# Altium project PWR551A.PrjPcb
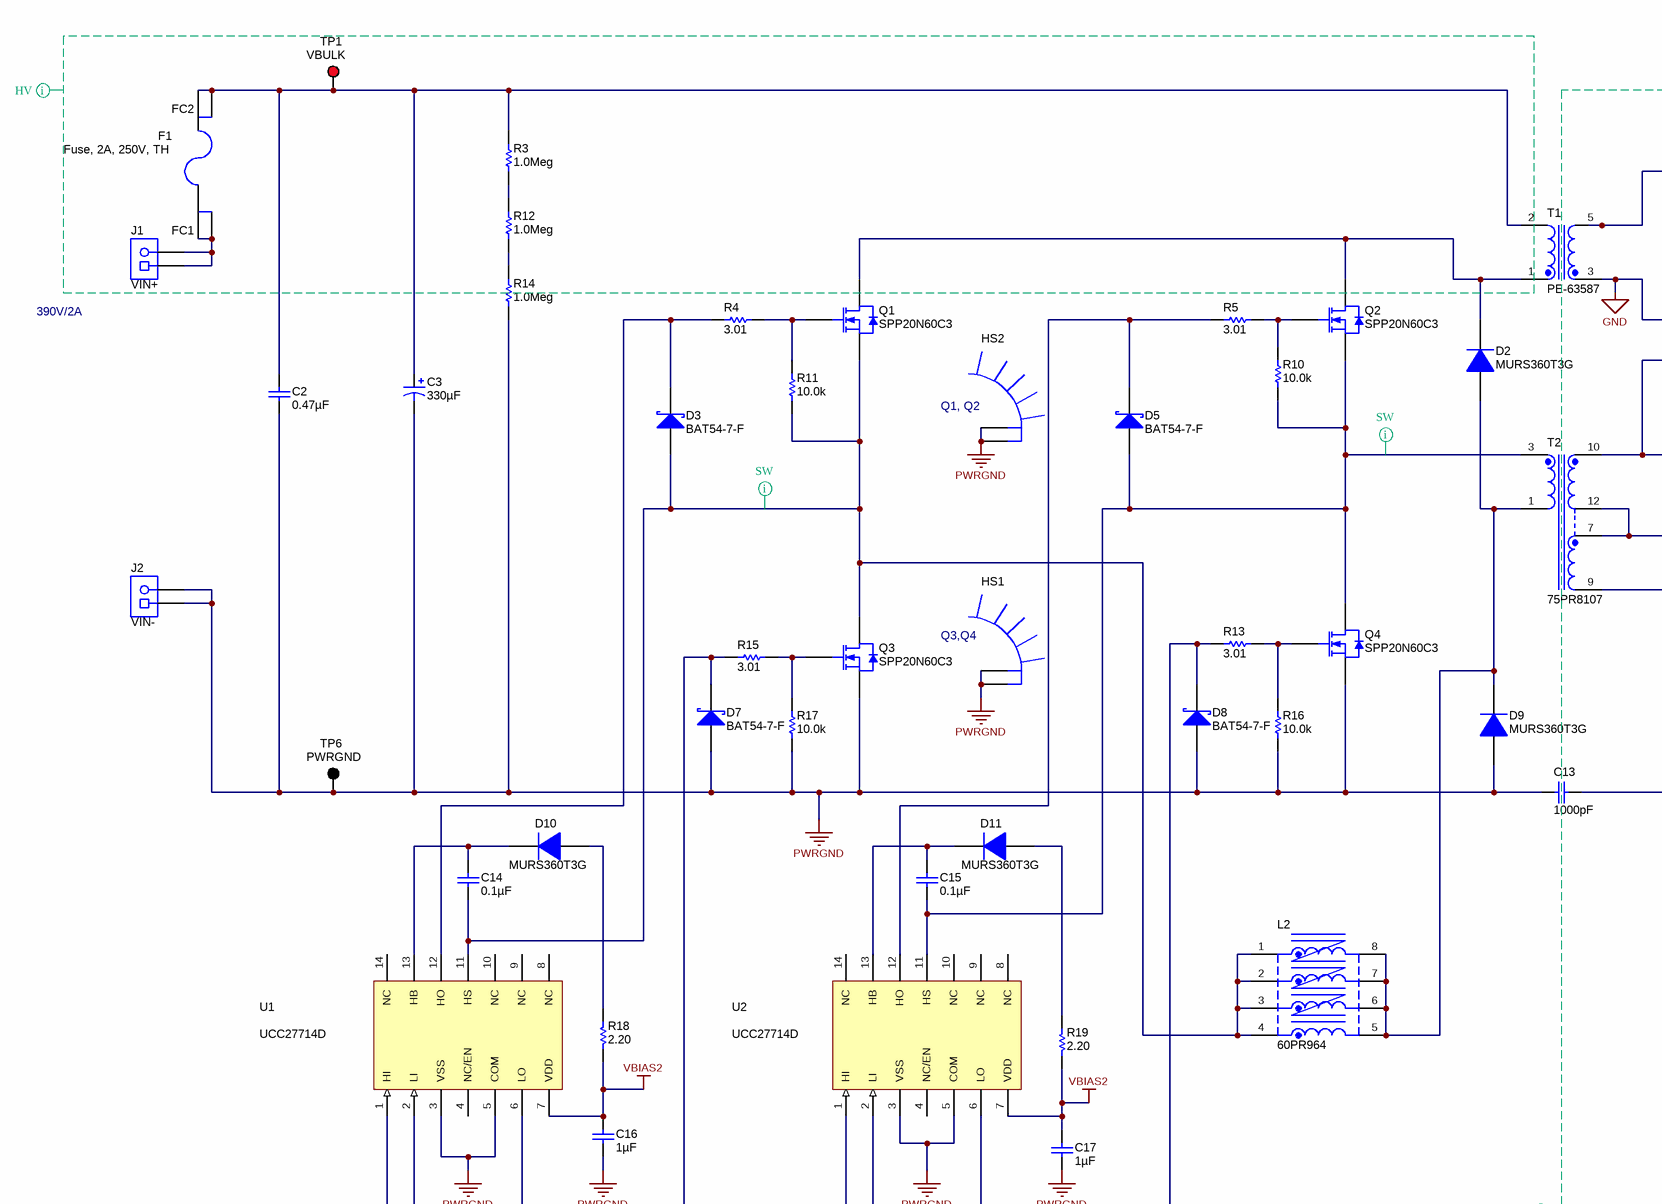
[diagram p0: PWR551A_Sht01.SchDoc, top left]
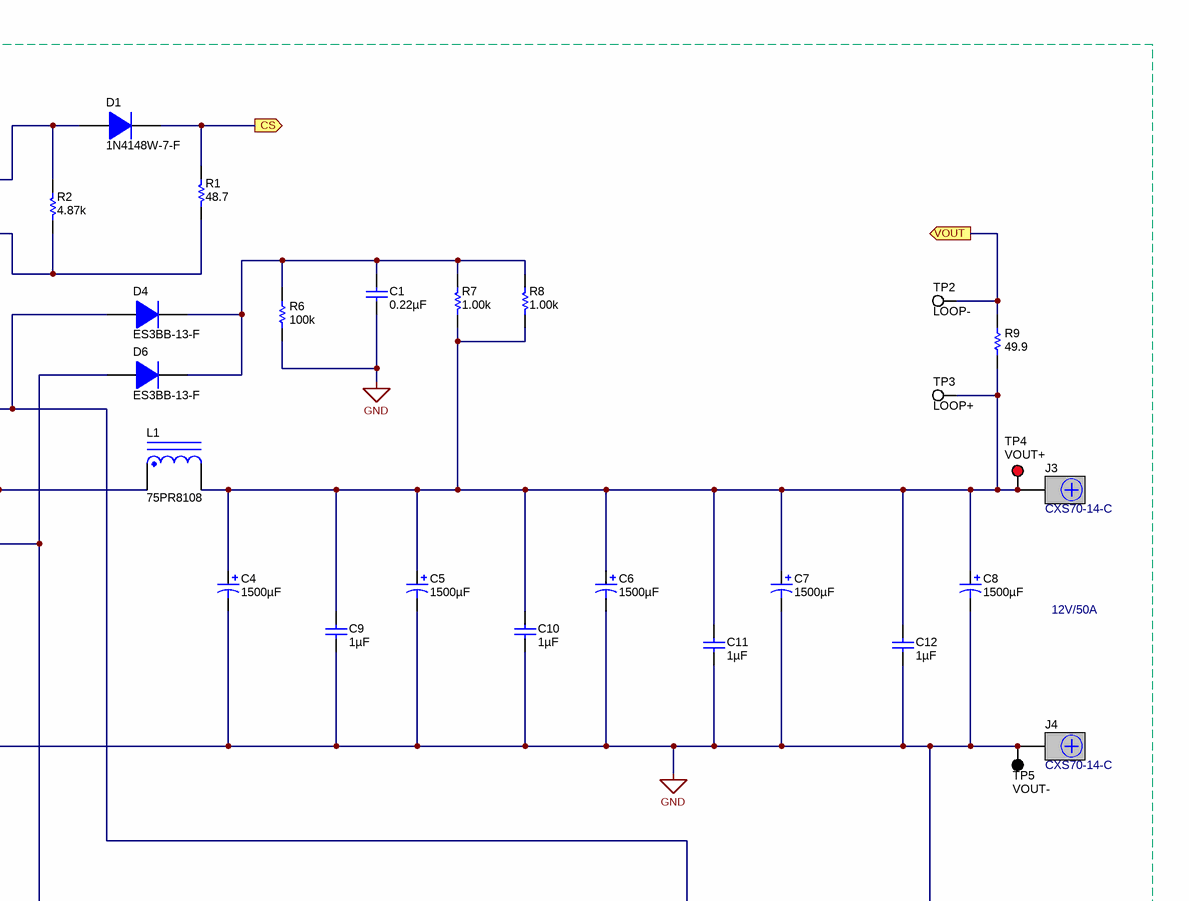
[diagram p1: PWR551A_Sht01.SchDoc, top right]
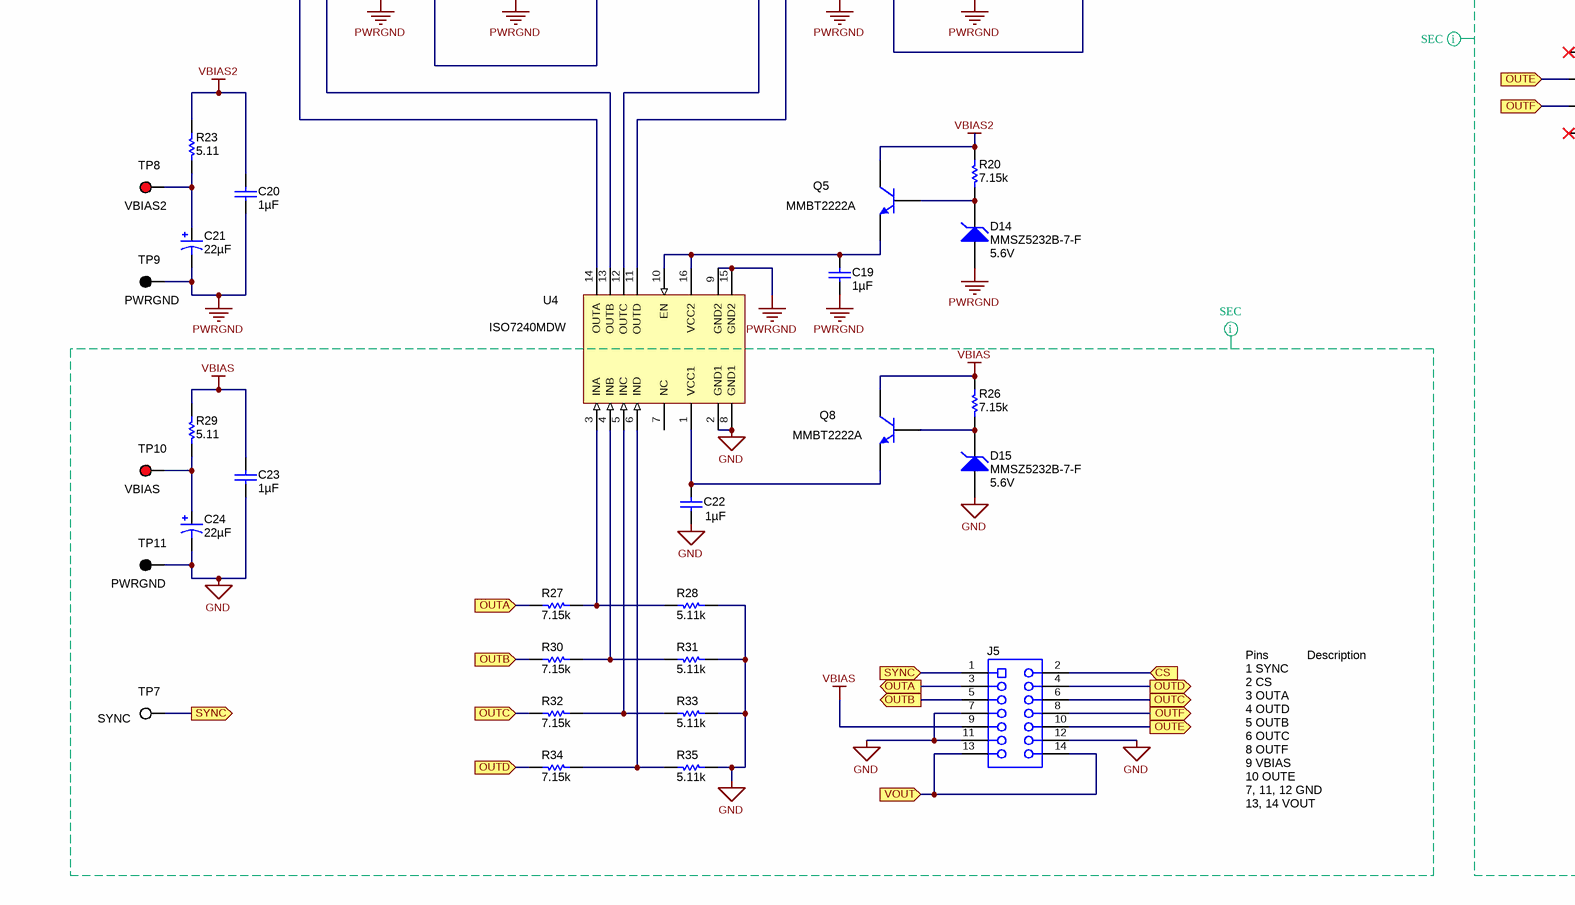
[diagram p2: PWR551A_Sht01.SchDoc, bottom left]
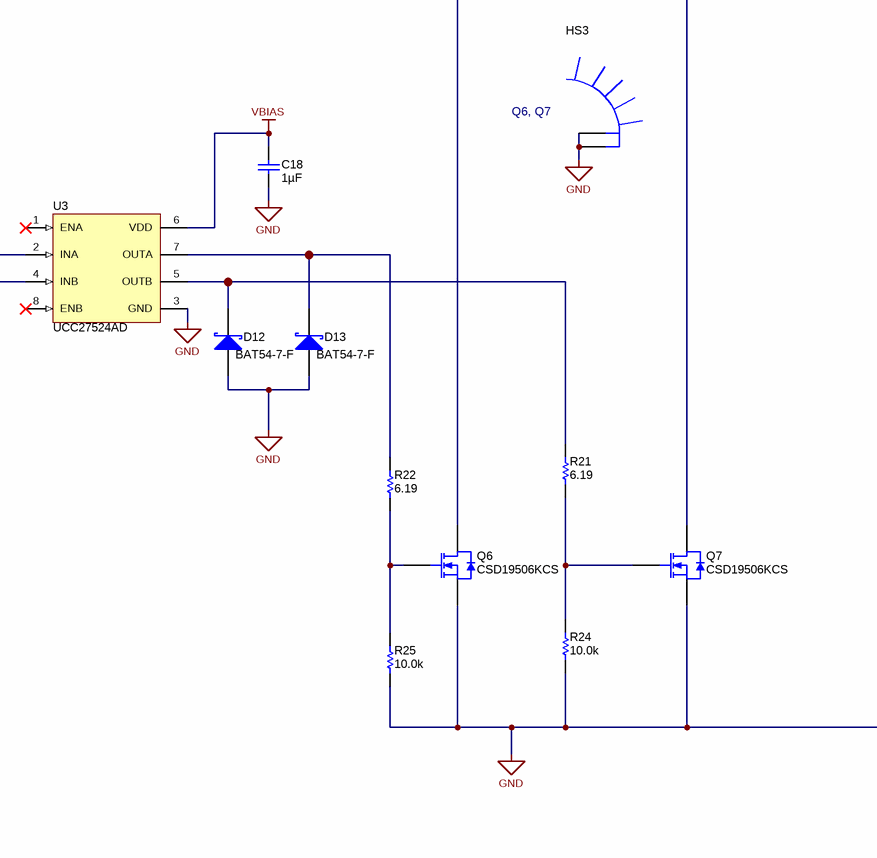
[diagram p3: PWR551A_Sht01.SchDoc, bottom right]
CopyrightYear: 2014; PCB_Layout: Brian Gaynor/Michael Rodgers; PCB_Rev: A; PRJ_Customer: Public Release; PRJ_Engineer: Mike O'Loughlin; PRJ_Number: PWR551; PRJ_Title: UCC27714EVM-551; SCH_Rev: A; TechSupport: http://www.ti.com/support
2 sheets, 162 parts. Net scope: flat (ports and power ports of the same name join across sheets).
Board file: PWR551A.PcbDoc
Sheets:
  PWR551A_Sht01.SchDoc
  PWR551A_Hardware.SchDoc

## Sheet PWR551A_Sht01.SchDoc
size 558 x 431 mm; Date: Not shown in title block; ApprovedBy: Not shown in title block; CheckedBy: Not shown in title block; Author: Not shown in title block; CompanyName: Not shown in title block; DrawnBy: Mike O'Loughlin; Engineer: Not shown in title block; Organization: Not shown in title block; Address1: Not shown in title block; Address2: Not shown in title block; Address3: Not shown in title block; Address4: Not shown in title block; DocumentNumber: 1; Revision: Use project parameter SCH_Rev; SheetNumber: 1; SheetTotal: 2; PageSetup: Record=PageOptions|CenterHorizontal=True|CenterVertical=True|PrintScale=1.00|XCorrection=1.00|YCorrection=1.00|PrintKind=0|BorderSize=5000000|LeftOffset=0|BottomOffset=0|Orientation=2|PaperLength=1000|PaperWidth=1000|Scale=100|PaperSource=15|PrintQuality=600|MediaType=1|DitherType=10|PaperKind=Letter|PrintScaleMode=1

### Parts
C1  ValueDisplayed: 0.22µF  [2220]  (hidden comment: C2220C224J1GACTU)
C2  ValueDisplayed: 0.47µF  [CAPRR2250W80L2550T850H1750]  (hidden comment: ECQ-U2A474ML)
C3  ValueDisplayed: 330µF  [TS-HC_3500x3500]  (hidden comment: EET-HC2W331EA)
C4  ValueDisplayed: 1500µF  [KY_1000x3000]  (hidden comment: EKY-160ELL152MJ30S)
C5  ValueDisplayed: 1500µF  [KY_1000x3000]  (hidden comment: EKY-160ELL152MJ30S)
C6  ValueDisplayed: 1500µF  [KY_1000x3000]  (hidden comment: EKY-160ELL152MJ30S)
C7  ValueDisplayed: 1500µF  [KY_1000x3000]  (hidden comment: EKY-160ELL152MJ30S)
C8  ValueDisplayed: 1500µF  [KY_1000x3000]  (hidden comment: EKY-160ELL152MJ30S)
C9  ValueDisplayed: 1µF  [1206]  (hidden comment: C3216X7R1E105K085AA)
C10  ValueDisplayed: 1µF  [1206]  (hidden comment: C3216X7R1E105K085AA)
C11  ValueDisplayed: 1µF  [1206]  (hidden comment: C3216X7R1E105K085AA)
C12  ValueDisplayed: 1µF  [1206]  (hidden comment: C3216X7R1E105K085AA)
C13  ValueDisplayed: 1000pF  [440L_930x1250]  (hidden comment: 440LD10-R)
C14  ValueDisplayed: 0.1µF  [0805_HV]  (hidden comment: C2012X7R1H104K)
C15  ValueDisplayed: 0.1µF  [0805_HV]  (hidden comment: C2012X7R1H104K)
C16  ValueDisplayed: 1µF  [0805_HV]  (hidden comment: C2012X7R1E105K)
C17  ValueDisplayed: 1µF  [0805_HV]  (hidden comment: C2012X7R1E105K)
C18  ValueDisplayed: 1µF  [0805_HV]  (hidden comment: C2012X7R1E105K)
C19  ValueDisplayed: 1µF  [0805_HV]  (hidden comment: C2012X7R1E105K)
C20  ValueDisplayed: 1µF  [0805_HV]  (hidden comment: C2012X7R1E105K)
C21  ValueDisplayed: 22µF  [M_500x1100]  (hidden comment: ECA-1VM220)
C22  ValueDisplayed: 1µF  [0805_HV]  (hidden comment: C2012X7R1E105K)
C23  ValueDisplayed: 1µF  [0805_HV]  (hidden comment: C2012X7R1E105K)
C24  ValueDisplayed: 22µF  [M_500x1100]  (hidden comment: ECA-1VM220)
D1  1N4148W-7-F  [SOD-123]
D2  MURS360T3G  [SMC]
D3  BAT54-7-F  [SOT-23]
D4  ES3BB-13-F  [SMB]
D5  BAT54-7-F  [SOT-23]
D6  ES3BB-13-F  [SMB]
D7  BAT54-7-F  [SOT-23]
D8  BAT54-7-F  [SOT-23]
D9  MURS360T3G  [SMC]
D10  MURS360T3G  [SMC]
D11  MURS360T3G  [SMC]
D12  BAT54-7-F  [SOT-23]
D13  BAT54-7-F  [SOT-23]
D14  MMSZ5232B-7-F  value 5.6V  [SOD-123]
D15  MMSZ5232B-7-F  value 5.6V  [SOD-123]
F1  Fuse, 2A, 250V, TH  (mechanical)
FC1  01000056Z  [Littelfuse_0100-0020_54_56]  (value not drawn)
FC2  01000056Z  [Littelfuse_0100-0020_54_56]  (value not drawn)
HS1  782653B02000G  [HEATSINK_782653B02000G]  (value not drawn)
HS2  782653B02000G  [HEATSINK_782653B02000G]  (value not drawn)
HS3  782653B02000G  [HEATSINK_782653B02000G]  (value not drawn)
J1  VIN+  [CONN_ED120-2DS]
J2  VIN-  [CONN_ED120-2DS]
J3  CXS70-14-C  [Panduit_CXS70-14-C]
J4  CXS70-14-C  [Panduit_CXS70-14-C]
J5  DF11-14DS-2DSA(05)  [Hirose_DF11-14DS-2DSA[05]]  (value not drawn)
L1  75PR8108  [75P]
L2  60PR964  [60P]
Q1  SPP20N60C3  [TO-220AB_100mil]
Q2  SPP20N60C3  [TO-220AB_100mil]
Q3  SPP20N60C3  [TO-220AB_100mil]
Q4  SPP20N60C3  [TO-220AB_100mil]
Q5  MMBT2222A  [SOT-23]
Q6  CSD19506KCS  [TO-220AB_100mil]
Q7  CSD19506KCS  [TO-220AB_100mil]
Q8  MMBT2222A  [SOT-23]
R1  value 48.7  [0805_HV]  (hidden comment: CRCW080548R7FKEA)
R2  value 4.87k  [0805_HV]  (hidden comment: ERJ-6ENF4871V)
R3  value 1.0Meg  [1206]  (hidden comment: CRCW12061M00JNEA)
R4  value 3.01  [0805_HV]  (hidden comment: CRCW08053R01FKEA)
R5  value 3.01  [0805_HV]  (hidden comment: CRCW08053R01FKEA)
R6  ValueDisplayed: 100k  [2512]  (hidden comment: CRCW2512100KFKEG)
R7  value 1.00k  [4527_450]  (hidden comment: WSC45271K000FEA)
R8  value 1.00k  [4527_450]  (hidden comment: WSC45271K000FEA)
R9  ValueDisplayed: 49.9  [0805_HV]  (hidden comment: ERJ-6ENF49R9V)
R10  value 10.0k  [0805_HV]  (hidden comment: ERJ-6ENF1002V)
R11  value 10.0k  [0805_HV]  (hidden comment: ERJ-6ENF1002V)
R12  value 1.0Meg  [1206]  (hidden comment: CRCW12061M00JNEA)
R13  value 3.01  [0805_HV]  (hidden comment: CRCW08053R01FKEA)
R14  value 1.0Meg  [1206]  (hidden comment: CRCW12061M00JNEA)
R15  value 3.01  [0805_HV]  (hidden comment: CRCW08053R01FKEA)
R16  value 10.0k  [0805_HV]  (hidden comment: ERJ-6ENF1002V)
R17  value 10.0k  [0805_HV]  (hidden comment: ERJ-6ENF1002V)
R18  value 2.20  [0805_HV]  (hidden comment: ERJ-6RQF2R2V)
R19  value 2.20  [0805_HV]  (hidden comment: ERJ-6RQF2R2V)
R20  value 7.15k  [0805_HV]  (hidden comment: ERJ-6ENF7151V)
R21  value 6.19  [0805_HV]  (hidden comment: CRCW08056R19FKEA)
R22  value 6.19  [0805_HV]  (hidden comment: CRCW08056R19FKEA)
R23  value 5.11  [0805_HV]  (hidden comment: CRCW08055R11FKEA)
R24  value 10.0k  [0805_HV]  (hidden comment: ERJ-6ENF1002V)
R25  value 10.0k  [0805_HV]  (hidden comment: ERJ-6ENF1002V)
R26  value 7.15k  [0805_HV]  (hidden comment: ERJ-6ENF7151V)
R27  value 7.15k  [0805_HV]  (hidden comment: ERJ-6ENF7151V)
R28  value 5.11k  [0805_HV]  (hidden comment: ERJ-6ENF5111V)
R29  value 5.11  [0805_HV]  (hidden comment: CRCW08055R11FKEA)
R30  value 7.15k  [0805_HV]  (hidden comment: ERJ-6ENF7151V)
R31  value 5.11k  [0805_HV]  (hidden comment: ERJ-6ENF5111V)
R32  value 7.15k  [0805_HV]  (hidden comment: ERJ-6ENF7151V)
R33  value 5.11k  [0805_HV]  (hidden comment: ERJ-6ENF5111V)
R34  value 7.15k  [0805_HV]  (hidden comment: ERJ-6ENF7151V)
R35  value 5.11k  [0805_HV]  (hidden comment: ERJ-6ENF5111V)
T1  PE-63587  [Pulse_PE6358X]
T2  75PR8107  [VITEC_75PR8107]
TP1  VBULK  [Keystone5000]
TP2  LOOP-  [Keystone5002]
TP3  LOOP+  [Keystone5002]
TP4  VOUT+  [Keystone5000]
TP5  VOUT-  [Keystone5001]
TP6  PWRGND  [Keystone5001]
TP7  SYNC  [Keystone5002]
TP8  VBIAS2  [Keystone5000]
TP9  PWRGND  [Keystone5001]
TP10  VBIAS  [Keystone5000]
TP11  PWRGND  [Keystone5001]
U1  UCC27714D  [D0014A_N]
U2  UCC27714D  [D0014A_N]
U3  UCC27524AD  [D0008A_N]
U4  ISO7240MDW  [DW0016A_N]

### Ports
CS (in), CS (out), OUTA (in), OUTA (out), OUTB (in), OUTB (out), OUTC (in), OUTC (out), OUTD (in), OUTD (out), OUTE (in), OUTE (out), OUTF (in), OUTF (out), SYNC (in), SYNC (out), VOUT (in), VOUT (out)

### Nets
GND: C1.1 C4.2(-) C5.2(-) C6.2(-) C7.2(-) C8.2(-) C9.1 C10.1 C11.1 C12.1 C13.1 C18.1 C22.1 C23.1 C24.2(-) D12.1(A) D13.1(A) D15.2(A) HS3.1 HS3.2 J4.1 J5.7 J5.11 J5.12 Q6.3(S) Q7.3(S) R1.2 R2.2 R6.2 R24.2 R25.2 R28.1 R31.1 R33.1 R35.1 T1.3 TP5.1 TP11.1 U3.3(GND) U4.2(GND1) U4.8(GND1)
PWRGND: C2.1 C3.2(-) C13.2 C16.1 C17.1 C19.1 C20.1 C21.2(-) D7.1(A) D8.1(A) D9.2(A) D14.2(A) HS1.1 HS1.2 HS2.1 HS2.2 J2.1 J2.2 Q3.3(S) Q4.3(S) R14.1 R16.2 R17.2 TP6.1 TP9.1 U1.3(VSS) U1.5(COM) U2.3(VSS) U2.5(COM) U4.9(GND2) U4.15(GND2)
VBIAS: C18.2 C23.2 J5.9 Q8.3(C) R26.1 R29.1 U3.6(VDD)
VBIAS2: C16.2 C17.2 C20.2 Q5.3(C) R18.1 R19.1 R20.1 R23.1 U1.7(VDD) U2.7(VDD)
CS: D1.1(K) J5.2 R1.1 ; port CS
OUTA: J5.3 R27.1 ; port OUTA
OUTB: J5.5 R30.1 ; port OUTB
OUTC: J5.6 R32.1 ; port OUTC
OUTD: J5.4 R34.1 ; port OUTD
OUTE: J5.10 U3.2(INA) ; port OUTE
OUTF: J5.8 U3.4(INB) ; port OUTF
SYNC: J5.1 TP7.1 ; port SYNC
VOUT: J5.13 J5.14 R9.1 TP2.1 ; port VOUT
NetC1_2: C1.2 D4.1(K) D6.1(K) R6.1 R7.2 R8.2
NetC2_2: C2.2 C3.1(+) FC2.1 FC2.2 R3.2 T1.2 TP1.1
NetC4_1: C4.1(+) C5.1(+) C6.1(+) C7.1(+) C8.1(+) C9.2 C10.2 C11.2 C12.2 J3.1 L1.14 R7.1 R8.1 R9.2 TP3.1 TP4.1
NetC14_1: C14.1 D3.1(A) L2.1 L2.2 L2.3 L2.4 Q1.3(S) Q3.2(D) R11.2 U1.11(HS)
NetC14_2: C14.2 D10.1(K) U1.13(HB)
NetC15_1: C15.1 D5.1(A) Q2.3(S) Q4.2(D) R10.1 T2.3 U2.11(HS)
NetC15_2: C15.2 D11.1(K) U2.13(HB)
NetC19_2: C19.2 Q5.2(E) U4.10(EN) U4.16(VCC2)
NetC21_1: C21.1(+) R23.2 TP8.1
NetC22_2: C22.2 Q8.2(E) U4.1(VCC1)
NetC24_1: C24.1(+) R29.2 TP10.1
NetD1_2: D1.2(A) R2.1 T1.5
NetD2_1: D2.1(K) Q1.2(D) Q2.2(D) T1.1
NetD2_2: D2.2(A) D9.1(K) L2.5 L2.6 L2.7 L2.8 T2.1
NetD3_3: D3.3(K) R4.1 U1.12(HO)
NetD4_2: D4.2(A) Q7.2(D) T2.10
NetD5_3: D5.3(K) R5.1 U2.12(HO)
NetD6_2: D6.2(A) Q6.2(D) T2.9
NetD7_3: D7.3(K) R15.1 U1.6(LO)
NetD8_3: D8.3(K) R13.1 U2.6(LO)
NetD10_2: D10.2(A) R18.2
NetD11_2: D11.2(A) R19.2
NetD12_3: D12.3(K) R21.1 U3.5(OUTB)
NetD13_3: D13.3(K) R22.1 U3.7(OUTA)
NetD14_1: D14.1(K) Q5.1(B) R20.2
NetD15_1: D15.1(K) Q8.1(B) R26.2
NetFC1_1: FC1.1 FC1.2 J1.1 J1.2
NetL1_13: L1.13 T2.7 T2.12
NetQ1_1: Q1.1(G) R4.2 R11.1
NetQ2_1: Q2.1(G) R5.2 R10.2
NetQ3_1: Q3.1(G) R15.2 R17.1
NetQ4_1: Q4.1(G) R13.2 R16.1
NetQ6_1: Q6.1(G) R22.2 R25.1
NetQ7_1: Q7.1(G) R21.2 R24.1
NetR3_1: R3.1 R12.2
NetR12_1: R12.1 R14.2
NetR27_2: R27.2 R28.2 U4.3(INA)
NetR30_2: R30.2 R31.2 U4.4(INB)
NetR32_2: R32.2 R33.2 U4.5(INC)
NetR34_2: R34.2 R35.2 U4.6(IND)
NetU1_1: U1.1(HI) U4.14(OUTA)
NetU1_2: U1.2(LI) U4.13(OUTB)
NetU2_1: U2.1(HI) U4.12(OUTC)
NetU2_2: U2.2(LI) U4.11(OUTD)

Not connected (* = marked no-connect by the designer): F1 1 2; U1 4(NC/EN) 8(NC) 9(NC) 10(NC) 14(NC); U2 4(NC/EN) 8(NC) 9(NC) 10(NC) 14(NC); U3 1(ENA)* 8(ENB)*; U4 7(NC)

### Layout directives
net class SEC: GND, VBIAS
net class HV: (no net found under the mark)
net class SW: NetC14_1, NetC15_1

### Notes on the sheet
- 390V/2A
- (near HS2) Q1, Q2
- (near HS1) Q3,Q4
- 12V/50A
- Q6, Q7
- Pins           Description
  1	SYNC
  2	CS
  3	OUTA
  4	OUTD
  5	OUTB
  6	OUTC
  8	OUTF
  9	VBIAS
  10	OUTE
  7, 11, 12	GND
  13, 14	VOUT

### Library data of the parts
C1 = C2220C224J1GACTU: CAP, CERM, 0.22uF, 100V, +/-5%, C0G/NP0, 2220; Manufacturer: Kemet; Polarized: N; CompType: Capacitor; U/M: EA; Cap_F: 0.00000022; Tolerance_%: 5; Value1: Unknown; VDC_V: 100; TaMin_C: -55; TaMax_C: 125
C2 = ECQ-U2A474ML: CAP, Film, 0.47uF, 275V, +/-20%, TH; Manufacturer: Panasonic; Polarized: N; CompType: Capacitor; U/M: EA; Cap_F: 0.00000047; Tolerance_%: 20; Value1: Unknown; VDC_V: 275; TaMin_C: -40; TaMax_C: 100; Cap_Case: Radial 25x8.5x18.5
C3 = EET-HC2W331EA: CAP, AL, 330uF, 450V, +/-20%, 0.553 ohm, TH; Manufacturer: Panasonic; Polarized: Y; CompType: Capacitor; U/M: EA; Cap_F: 0.00033; Tolerance_%: 20; VDC_V: 450; ESR_Ohm: 0.553; IRMS_A: 1.38; TaMin_C: -25; TaMax_C: 105; Cap_Case: 35x35
C4-C8 = EKY-160ELL152MJ30S: CAP, AL, 1500uF, 16V, +/-20%, 0.031 ohm, TH; Manufacturer: Nippon Chemi-Con; Polarized: Y; CompType: Capacitor; U/M: EA; Cap_F: 0.0015; Tolerance_%: 20; VDC_V: 16; ESR_Ohm: 0.031; IRMS_A: 1.91; TaMin_C: -40; TaMax_C: 105; Cap_Case: 10x30
C9-C12 = C3216X7R1E105K/0.85: CAP, CERM, 1 µF, 25 V, +/- 10%, X7R, 1206; Manufacturer: TDK; Value: 1uF; Polarized: N; CompType: Capacitor; U/M: EA; Cap_F: 0.000001; Tolerance_%: 10; ESR_ohm: 0.01; Value1: 0.01 ohm; VDC_V: 25; Value2: 25V; TaMin_C: -55; TaMax_C: 125
C13 = 440LD10-R: CAP, CERM, 1000pF, 400V, +/-20%, Y5U, Disc, 9.3x12.5mm; Manufacturer: Yageo America; Polarized: N; CompType: Capacitor; U/M: EA; Cap_F: 0.000000001; Tolerance_%: 20; Value1: Unknown; VDC_V: 400; TaMin_C: -30; TaMax_C: 125
C14 C15 = C2012X7R1H104K: CAP, CERM, 0.1uF, 50V, +/-10%, X7R, 0805; Manufacturer: TDK; Polarized: N; CompType: Capacitor; U/M: EA; Cap_F: 0.0000001; Tolerance_%: 10; Value1: Unknown; VDC_V: 50; TaMin_C: -55; TaMax_C: 125; Cap_Case: 0805
C16-C20 C22 C23 = C2012X7R1E105k: CAP, CERM, 1uF, 25V, +/-10%, X7R, 0805; Manufacturer: TDK; Polarized: N; CompType: Capacitor; U/M: EA; Cap_F: 0.000001; Tolerance_%: 10; ESR_Ohm: 0.0075; Value1: 0.0075 ohm; VDC_V: 25; TaMin_C: -55; TaMax_C: 125; Cap_Case: 0805
C21 C24 = ECA-1VM220: CAP, AL, 22uF, 35V, +/-20%, TH; Manufacturer: Panasonic; Polarized: Y; CompType: Capacitor; U/M: EA; Cap_F: 0.000022; Tolerance_%: 20; Value1: Unknown; VDC_V: 35; IRMS_A: 0.095; TaMin_C: -40; TaMax_C: 85; Cap_Case: 5x11
D1 = 1N4148W-7-F: Diode, Ultrafast, 100V, 0.15A, SOD-123; Manufacturer: Diodes Inc.; U/M: EA; Vf_V: 1.25; Value2: 1.25V; Io_A: 0.15; Vr_V: 100; TJmax_C: 150
D2 D9-D11 = MURS360T3G: Diode, Ultrafast, 600 V, 3 A, SMC; Manufacturer: ON Semiconductor; Value: 600V; U/M: EA; Vf_V: 1.25; Value1: 3A; Value2: 1.25V; Io_A: 3; Vr_V: 600; TJmax_C: 175; RJC_CperW: 11
D3 D5 D7 D8 D12 D13 = bat54-7-F: Diode, Schottky, 30V, 0.2A, SOT-23; Manufacturer: Diodes Inc.; U/M: EA; Vf_V: 0.65; Value2: 0.65V; Io_A: 0.2; Vr_V: 30; TJmax_C: 125
D4 D6 = ES3BB-13-F: Diode, Superfast Rectifier, 100V, 3A, SMB; Manufacturer: Diodes Inc.; U/M: EA; Vf_V: 0.9; Value2: 0.9V; Io_A: 3; Vr_V: 100
D14 D15 = MMSZ5232B-7-F: Diode, Zener, 5.6V, 500mW, SOD-123; Manufacturer: Diodes Inc.; SymbolCreator: a0412235; U/M: EA; Power_W: 0.5; Vz_V: 5.6; Value1: 0.5W; RJA_CperW: 350
F1 = BK/S501-2-R: Manufacturer: Cooper Bussman; U/M: EA; VDC_V: 250; Interrupt_AC: 1500; Irating_A: 2; Vdrop: 0.205
FC1 FC2 = 01000056Z: Fuse Holder, 10A, TH; Manufacturer: Littelfuse; SymbolCreator: a0411947
HS1-HS3 = 782653B02000G: HEATSINK VERT MAX CLIP, BLACK, 2 INCHES; Manufacturer: Aavid; SymbolCreator: a0799628
J1 J2 = ED120/2DS: TERMINAL BLOCK 5.08MM VERT 2POS, TH; Manufacturer: On-Shore Technology; SymbolCreator: a0412235; U/M: EA
J3 J4 = CXS70-14-C: Terminal 70A Lug; Manufacturer: Panduit; SymbolCreator: crossc; CompType: Screw Terminal; U/M: EA
J5 = DF11-14DS-2DSA(05): Receptacle, 7x2, 2mm, TH; Manufacturer: Hirose Electric Co. Ltd.; SymbolCreator: a0412235; U/M: EA
L1 = 75PR8108: Inductor, Shielded, ?, 2uH, A, 0.0009 ohm, TH; Manufacturer: Vitec Corporation; SymbolCreator: x0208325; Ind_H: 2.0E-6; ValueDisplayed: 2µH; DCR_ohm: 0.0009; U/M: EA
L2 = 60PR964: Inductor, Shielded, ?, 26uH, A, 0.027 ohm, TH; Manufacturer: Vitec Corporation; SymbolCreator: x0208325; Ind_H: 26.0E-6; ValueDisplayed: 26µH; DCR_ohm: 0.027; U/M: EA
Q1-Q4 = SPP20N60C3: MOSFET, N-CH, 650V, 20.7A, TO-220AB; Manufacturer: Infineon Technologies; Alternate Manufacturer: None; U/M: EA; ChType: N; VdsMax_V: 650; Value1: 0.19 ohm; Rdson45_Ohm: 0.19; Value2: 114 nC; QgTyp_nC: 114; Vgs_V: 3.9; IdsMax_A: 20.7
Q5 Q8 = MMBT2222A, Fairchild Semiconductor: Transistor, NPN, 40V, 0.15A, SOT-23; Value: 0.3V; CompType: BJT; PNP: 0; NPN: 1; Vceo_V: 40; Vcesat1_V: 0.3; IcRated_A: 0.15; HfeMax: 300; TaMin_C: -55; TaMax_C: 150; U/M: EA
Q6 Q7 = CSD19506KCS: MOSFET, N-CH, 80V, 100A, TO-220AB; Manufacturer: Texas Instruments; Alternate Manufacturer: None; U/M: EA; ChType: N; VdsMax_V: 80; Value1: ? ohm; Value2: 120 nC; QgTyp_nC: 120; Vgs_V: 20; IdsMax_A: 100
R1 = crcw080548r7fkea: RES, 48.7 ohm, 1%, 0.125W, 0805; Manufacturer: Vishay-Dale; CompType: Resistor; Value_Code: 48R7; Tolerance_%: 1; Power_W: 0.125; VDC_V: 150; TempCo: 100 ppm/C; EIA_Code: E96; U/M: EA
R2 = ERJ-6ENF4871V: RES, 4.87k ohm, 1%, 0.125W, 0805; Manufacturer: Panasonic; CompType: Resistor; Res_ohm: 4870; Value_Code: 4k87; Tolerance_%: 1; Power_W: 0.125; TempCo: 100 ppm/C; EIA_Code: E96; U/M: EA
R3 R12 R14 = CRCW12061M00JNEA: RES, 1.0Meg ohm, 5%, 0.25W, 1206; Manufacturer: Vishay-Dale; CompType: Resistor; Res_ohm: 1000000; Value_Code: 1M00; Tolerance_%: 5; Power_W: 0.25; VDC_V: 200; TempCo: 200 ppm/C; EIA_Code: E24; U/M: EA
R4 R5 R13 R15 = CRCW08053R01FKEA: RES, 3.01 ohm, 1%, 0.125W, 0805; Manufacturer: Vishay-Dale; CompType: Resistor; Value_Code: 3R01; Tolerance_%: 1; Power_W: 0.125; VDC_V: 150; TempCo: 100 ppm/C; EIA_Code: E96; U/M: EA
R6 = CRCW2512100KFKEG: RES, 100 k, 1%, 1 W, 2512; Manufacturer: Vishay-Dale; Value: 100k; CompType: Resistor; Res_ohm: 100000; Tolerance_%: 1; Value2: 1W; VDC_V: 500; TempCo: 100 ppm/C; EIA_Code: E96; U/M: EA
R7 R8 = WSC45271K000FEA: RES, 1.00k ohm, 1%, 2W, 4527; Manufacturer: Vishay-Dale; CompType: Resistor; Res_ohm: 1000; Value_Code: 1k00; Tolerance_%: 1; Power_W: 2; TempCo: 20 ppm/C; EIA_Code: E96; U/M: EA
R9 = ERJ-6ENF49R9V: RES, 49.9, 1%, 0.125 W, 0805; Manufacturer: Panasonic; Value: 49.9; CompType: Resistor; Value_Code: 49R9; Tolerance_%: 1; Power_W: 0.125; Value2: 0.125W; VDC_V: 150; TempCo: 100 ppm/C; EIA_Code: E96; U/M: EA
R10 R11 R16 R17 R24 R25 = ERJ-6ENF1002V: RES, 10.0k ohm, 1%, 0.125W, 0805; Manufacturer: Panasonic; CompType: Resistor; Res_ohm: 10000; Value_Code: 10k0; Tolerance_%: 1; Power_W: 0.125; TempCo: 100 ppm/C; EIA_Code: E96; U/M: EA
R18 R19 = ERJ-6RQF2R2V: RES, 2.20 ohm, 1%, 0.125W, 0805; Manufacturer: Panasonic; CompType: Resistor; Res_ohm: 2.2; Value_Code: 2R20; Tolerance_%: 1; Power_W: 0.125; TempCo: 200 ppm/C; U/M: EA
R20 R26 R27 R30 R32 R34 = ERJ-6ENF7151V: RES, 7.15k ohm, 1%, 0.125W, 0805; Manufacturer: Panasonic; CompType: Resistor; Res_ohm: 7150; Value_Code: 7k15; Tolerance_%: 1; Power_W: 0.125; TempCo: 100 ppm/C; EIA_Code: E96; U/M: EA
R21 R22 = CRCW08056R19FKEA: RES, 6.19 ohm, 1%, 0.125W, 0805; Manufacturer: Vishay-Dale; CompType: Resistor; Value_Code: 6R19; Tolerance_%: 1; Power_W: 0.125; VDC_V: 150; TempCo: 100 ppm/C; EIA_Code: E96; U/M: EA
R23 R29 = CRCW08055R11FKEA: RES, 5.11 ohm, 1%, 0.125W, 0805; Manufacturer: Vishay-Dale; CompType: Resistor; Value_Code: 5R11; Tolerance_%: 1; Power_W: 0.125; VDC_V: 150; TempCo: 100 ppm/C; EIA_Code: E96; U/M: EA
R28 R31 R33 R35 = ERJ-6ENF5111V: RES, 5.11k ohm, 1%, 0.125W, 0805; Manufacturer: Panasonic; CompType: Resistor; Res_ohm: 5110; Value_Code: 5k11; Tolerance_%: 1; Power_W: 0.125; TempCo: 100 ppm/C; EIA_Code: E96; U/M: EA
T1 = PE-63587: Transformer, 20 mH, TH; Manufacturer: Pulse Engineering; SymbolCreator: a0799628; U/M: EA
T2 = 75PR8107: Transformer, 2.75mH, TH; Manufacturer: Vitec Corporation; SymbolCreator: x0208326; DCR_Ohm: 0.09; LeakageL: 15uH; U/M: EA
TP1 TP4 TP8 TP10 = 5000: Test Point, Miniature, Red, TH; Manufacturer: Keystone; CompType: Test Point Loop; U/M: EA
TP2 TP3 TP7 = 5002: Test Point, Miniature, White, TH; Manufacturer: Keystone; CompType: Test Point Loop; U/M: EA
TP5 TP6 TP9 TP11 = 5001: Test Point, Miniature, Black, TH; Manufacturer: Keystone; CompType: Test Point Loop; U/M: EA
U1 U2 = UCC27714D: High-Speed,4A, 600V High-side Low-side Gate Driver Device, D0014A; Alternate Manufacturer: None; Manufacturer: Texas Instruments; SymbolCreator: a0411947; CompType: IC; U/M: EA
U3 = UCC27524AD: Dual 5-A High-Speed Low-Side Gate Driver, D0008A; Manufacturer: Texas Instruments; Alternate Manufacturer: None; SymbolCreator: a0411947; CompType: IC; U/M: EA
U4 = ISO7240MDW: 150 Mbps Quad Channels, 4 / 0, Digital Isolator, 3.3 V / 5 V, -40 to +125 degC, 16-pin SOIC (DW), Green (RoHS & no Sb/Br); Manufacturer: Texas Instruments; Alternate PartNumber: Equivalent; Datarate(Mbps): 150; Input Noise Filter: None; Insulation Rating(VRMS): 2500; Prop Delay(Max)(ns): 16; Rating: Catalog; Supply Voltage(s)(V): 3.3, 5; TTL/CMOS Input Threshold: CMOS

## Sheet PWR551A_Hardware.SchDoc
size 431 x 279 mm; Date: Not shown in title block; ApprovedBy: Not shown in title block; CheckedBy: Not shown in title block; Author: Not shown in title block; CompanyName: Not shown in title block; DrawnBy: Mike O'Loughlin; Engineer: Not shown in title block; Organization: Not shown in title block; Address1: Not shown in title block; Address2: Not shown in title block; Address3: Not shown in title block; Address4: Not shown in title block; DocumentNumber: 2; Revision: Use project parameter SCH_Rev; SheetNumber: 2; SheetTotal: 2; PageSetup: Record=PageOptions|CenterHorizontal=True|CenterVertical=True|PrintScale=1.00|XCorrection=1.00|YCorrection=1.00|PrintKind=0|BorderSize=5000000|LeftOffset=0|BottomOffset=0|Orientation=2|PaperLength=1000|PaperWidth=1000|Scale=100|PaperSource=15|PrintQuality=600|MediaType=1|DitherType=10|PaperKind=Letter|PrintScaleMode=1
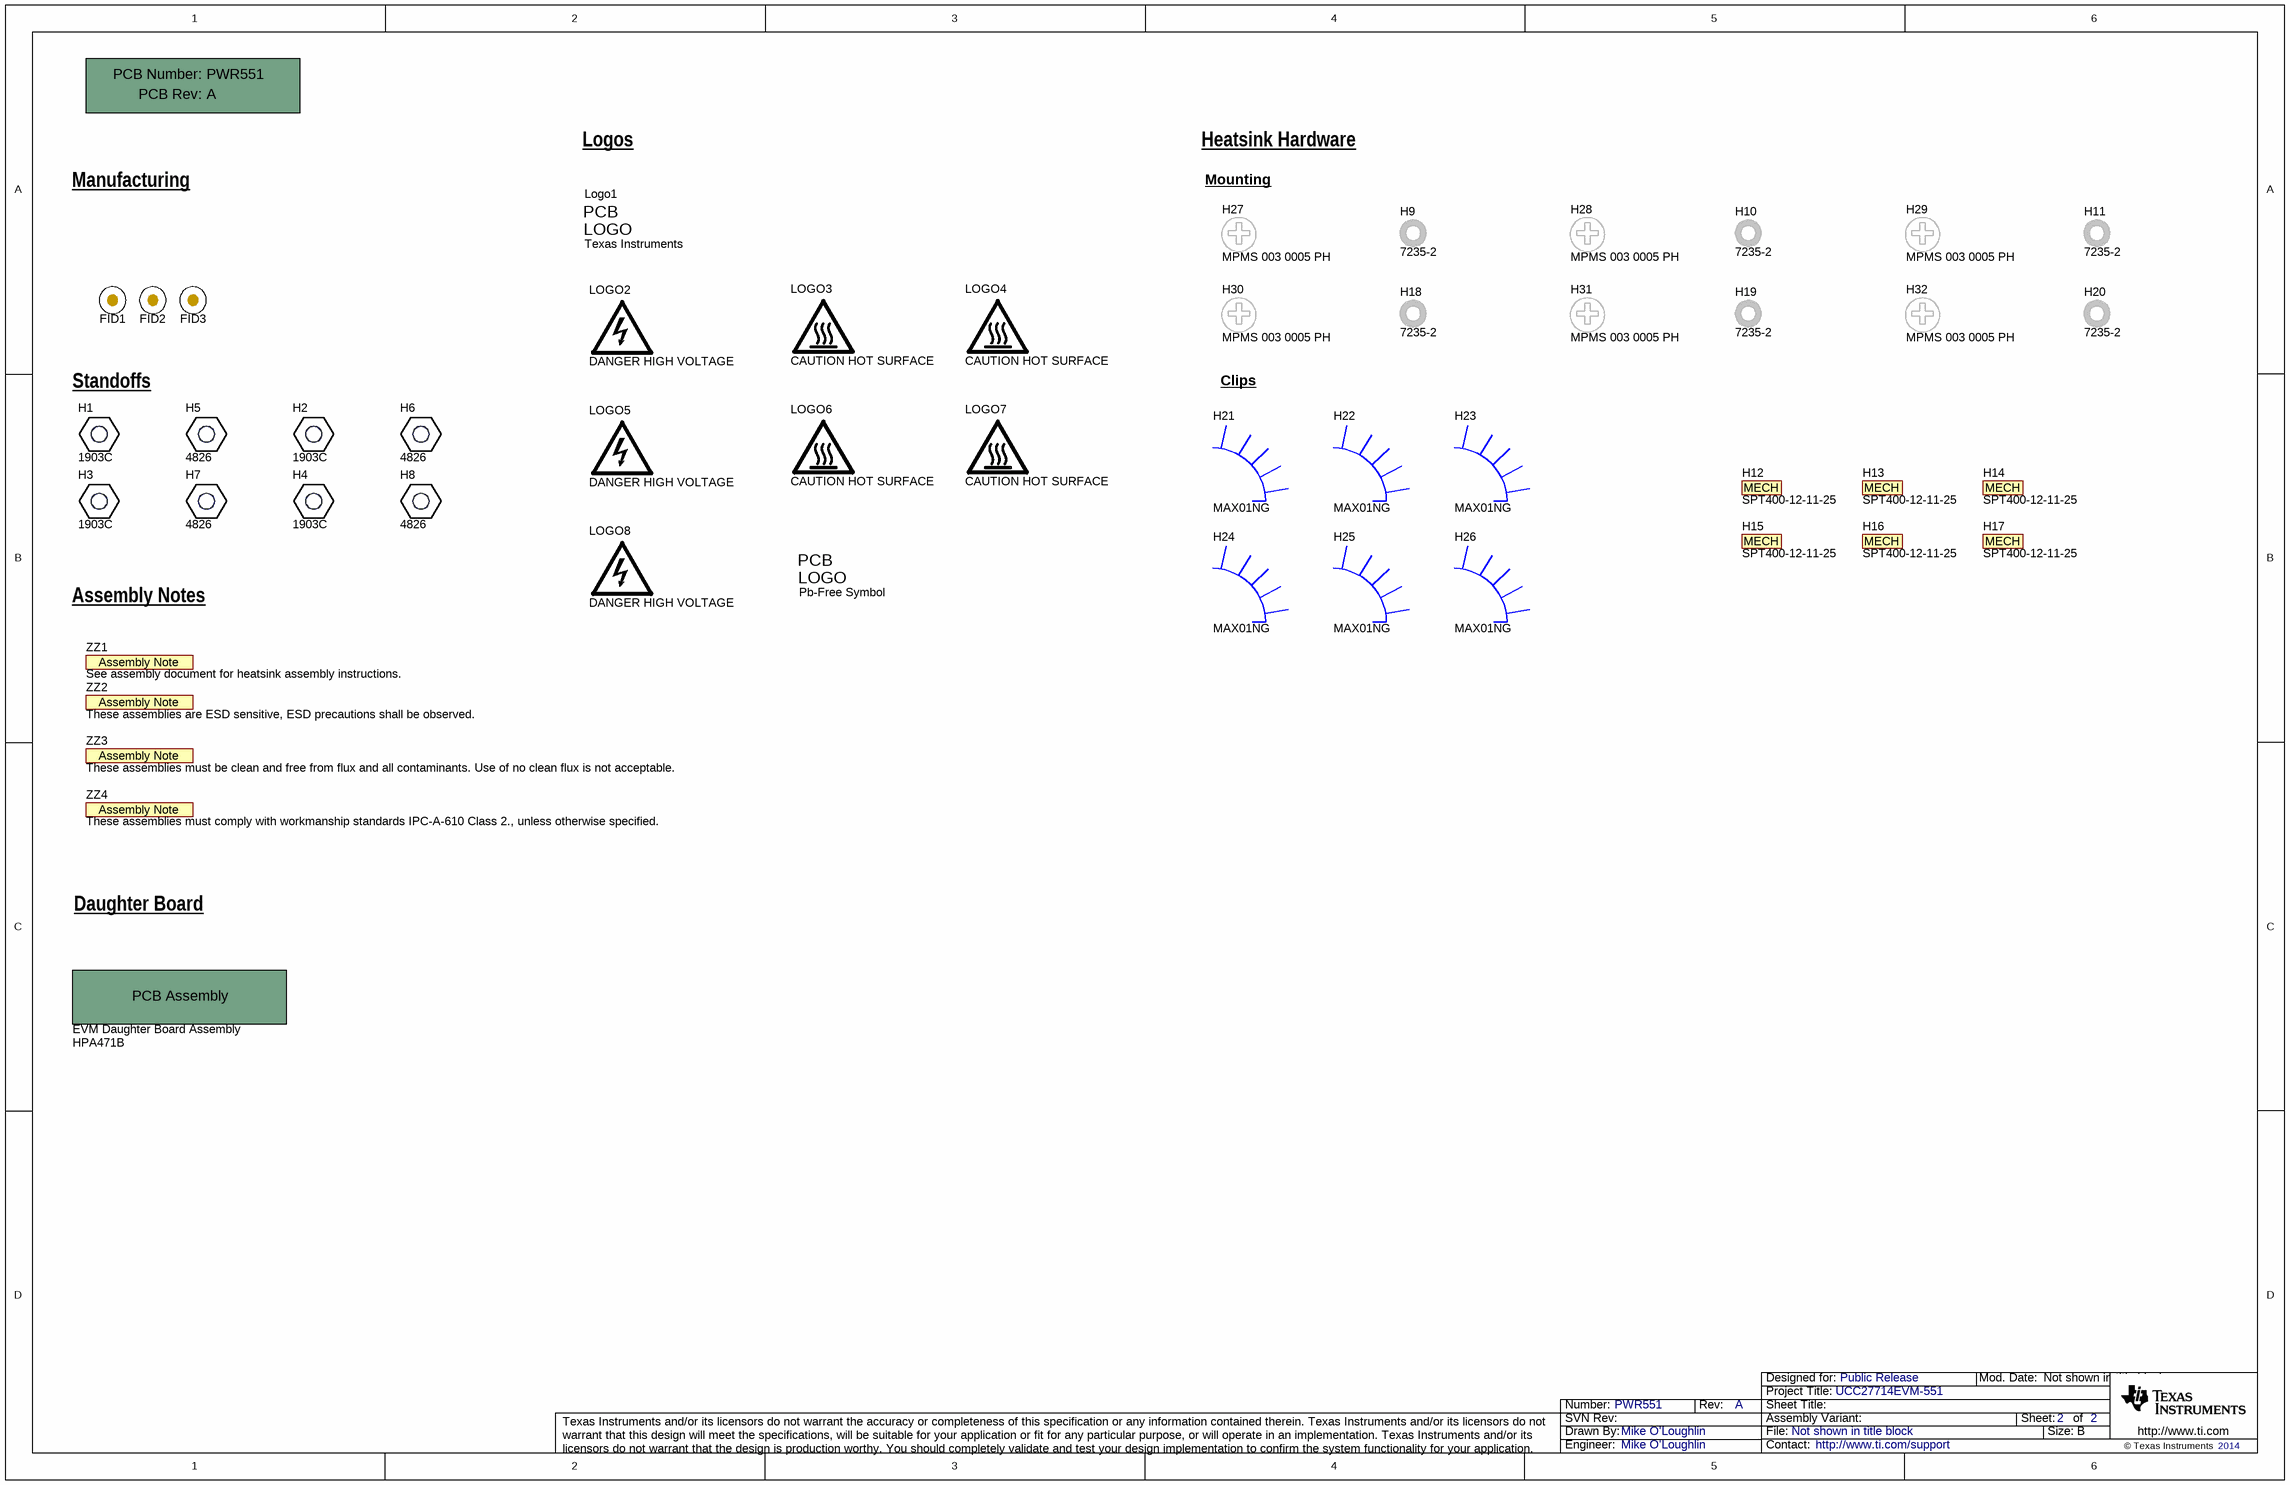
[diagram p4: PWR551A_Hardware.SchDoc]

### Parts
!PCB  Printed Circuit Board  (value not drawn)  (mechanical)
!PCBA1  EVM Daughter Board Assembly  PartNumber: HPA471B  (mechanical)
FID1  Fiducial  [Fiducial10-20]  (value not drawn)
FID2  Fiducial  [Fiducial10-20]  (value not drawn)
FID3  Fiducial  [Fiducial10-20]  (value not drawn)
H1  1903C  [KEYSTONE_1903C]
H2  1903C  [KEYSTONE_1903C]
H3  1903C  [KEYSTONE_1903C]
H4  1903C  [KEYSTONE_1903C]
H5  4826  [KEYSTONE_4826]
H6  4826  [KEYSTONE_4826]
H7  4826  [KEYSTONE_4826]
H8  4826  [KEYSTONE_4826]
H9  7235-2  (mechanical)
H10  7235-2  (mechanical)
H11  7235-2  (mechanical)
H12  SPT400-12-11-25  (mechanical)
H13  SPT400-12-11-25  (mechanical)
H14  SPT400-12-11-25  (mechanical)
H15  SPT400-12-11-25  (mechanical)
H16  SPT400-12-11-25  (mechanical)
H17  SPT400-12-11-25  (mechanical)
H18  7235-2  (mechanical)
H19  7235-2  (mechanical)
H20  7235-2  (mechanical)
H21  MAX01NG  (mechanical)
H22  MAX01NG  (mechanical)
H23  MAX01NG  (mechanical)
H24  MAX01NG  (mechanical)
H25  MAX01NG  (mechanical)
H26  MAX01NG  (mechanical)
H27  MPMS 003 0005 PH  [BuildingFastener_MPMS_003_0005_PH]
H28  MPMS 003 0005 PH  [BuildingFastener_MPMS_003_0005_PH]
H29  MPMS 003 0005 PH  [BuildingFastener_MPMS_003_0005_PH]
H30  MPMS 003 0005 PH  [BuildingFastener_MPMS_003_0005_PH]
H31  MPMS 003 0005 PH  [BuildingFastener_MPMS_003_0005_PH]
H32  MPMS 003 0005 PH  [BuildingFastener_MPMS_003_0005_PH]
Logo1  Texas Instruments  [TI_Stacked_Overlay_Medium]  (no BOM)
LOGO2  DANGER HIGH VOLTAGE  [IEC_HighVoltage_Small]  (no BOM)
LOGO3  CAUTION HOT SURFACE  [IEC_HotSurface_Small]  (no BOM)
LOGO4  CAUTION HOT SURFACE  [IEC_HotSurface_Small]  (no BOM)
LOGO5  DANGER HIGH VOLTAGE  [IEC_HighVoltage_Small]  (no BOM)
LOGO6  CAUTION HOT SURFACE  [IEC_HotSurface_Small]  (no BOM)
LOGO7  CAUTION HOT SURFACE  [IEC_HotSurface_Small]  (no BOM)
LOGO8  DANGER HIGH VOLTAGE  [IEC_HighVoltage_Small]  (no BOM)
Logo9  Pb-Free Symbol  [Pb-Free_Overlay_Medium]  (no BOM)
ZZ1  See assembly document for heatsink assembly instructions.  [AssemblyNote]  (no BOM)
ZZ2  These assemblies are ESD sensitive, ESD precautions shall be observed.  [AssemblyNote]  (no BOM)
ZZ3  These assemblies must be clean and free from flux and all contaminants. Use of no clean flux is not acceptable.  [AssemblyNote]  (no BOM)
ZZ4  These assemblies must comply with workmanship standards IPC-A-610 Class 2., unless otherwise specified.  [AssemblyNote]  (no BOM)

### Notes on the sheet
- Logos
- Heatsink Hardware
- Manufacturing
- (near H27) Mounting
- Standoffs
- Clips
- Assembly Notes
- Daughter Board

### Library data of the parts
!PCB = PCB: Manufacturer: Any; PartNumber: PWR551; SymbolCreator: a0412235
!PCBA1 = PCBA: Manufacturer: Texas Instruments; SymbolCreator: a0412235; U/M: EA
FID1-FID3 = Fiducial: Fiducial mark.  There is nothing to buy or mount.; SymbolCreator: codlsc
H1-H4 = 1903c: Standoff, Hex, 0.5"L #6-32 Nylon; Manufacturer: Keystone; SymbolCreator: a0412235
H5-H8 = 4826: HEX STANDOFF 6-32 NYLON 1-3/4"; Manufacturer: Keystone; SymbolCreator: a0412235
H9-H11 H18-H20 = 7235-2: Lock Washer, split, M3, Steel; Manufacturer: Keystone; SymbolCreator: a0412235
H12-H17 = SPT400-12-11-25: Silicon Thermal Pad, Tube 11x25mm; Manufacturer: Bergquist Company; SymbolCreator: codlsc
H21-H26 = MAX01NG: Heat Sink clip for TO-220; Manufacturer: Aavid; SymbolCreator: a0412235
H27-H32 = MPMS 003 0005 PH: MACHINE SCREW PAN PHILLIPS M3 5mm; Manufacturer: B&F Fastener Supply; CompType: Hardware
Logo1 = TI_Logo: Texas Instrument Corporate Signature; SymbolCreator: codlsc
LOGO2 LOGO5 LOGO8 = IEC_HighVoltage: IEC 61010-1 High Voltage Warning; SymbolCreator: a0412235
LOGO3 LOGO4 LOGO6 LOGO7 = IEC_HotSurface: IEC 61010-1 Hot Surface Warning; SymbolCreator: a0412235
Logo9 = Pb-Free: SymbolCreator: a0412235
ZZ1-ZZ4 = AssemblyNote: SymbolCreator: codlsc

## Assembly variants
001: not fitted FID1 FID2 FID3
